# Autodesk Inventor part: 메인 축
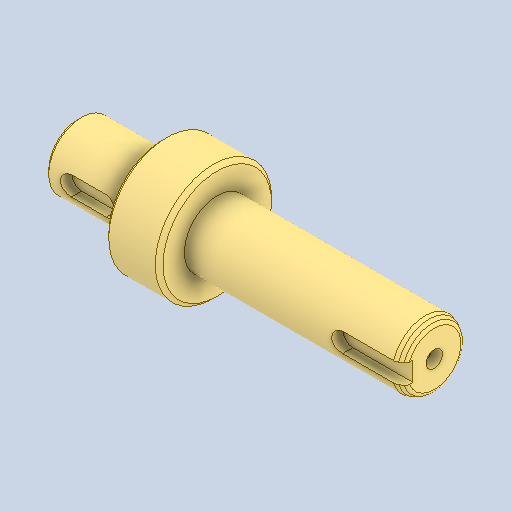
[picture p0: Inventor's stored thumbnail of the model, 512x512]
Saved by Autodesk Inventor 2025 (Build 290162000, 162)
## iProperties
Created: 2026-07
Part Number: 메인 축
Material: 강철, 탄소
Document SubType Name: Modeling
Designer: KDI
Density: 7.85 g/cm^3
Appearance: 기본값
Author: jhkim
Revision Number: 1
Sending System: Autodesk Inventor 2027
Preprocessor: ST-DEVELOPER v20.1
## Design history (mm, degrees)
feature "솔리드1"
node "솔리드2"
